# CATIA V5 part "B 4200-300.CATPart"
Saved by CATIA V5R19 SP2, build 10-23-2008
Part number: B 4200-300
Bounding box of the stored display mesh (mm): x -47.487 to 47.487, y -47.487 to 47.487, z 0 to 720
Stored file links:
  C:\Users\Bora\Desktop\3D Katı model\B serisi\B 4200\B 4200-300.CATPart
  C:\Program Files\Dassault Systemes\B19\intel_a\reffiles\standard\MetricThickPitch.txt
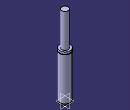
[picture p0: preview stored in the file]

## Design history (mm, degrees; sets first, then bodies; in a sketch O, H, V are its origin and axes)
Body1 (main body)
  Sketch1 on yz-plane, origin (0, 0, 0), H (0, 1, 0), V (0, 0, 1)
    point P1 (47.5, 398.5)
    point P2 (47.5, 393.5)
    point P3 (47.5, 398.5)
    point P6 (47.5, 393.5)
    point P9 (30, 719)
    point P11 (30, 719)
    arc A1 centre (47.5, 396) radius 2.5 from (47.5, 398.5) to (47.5, 393.5) ccw
    line L1 (47.5, 398.5) -> (47.5, 417)
    line L2 (47.5, 13) -> (47.5, 393.5)
    line L3 (43.5, 13) -> (43.5, 8)
    arc A2 centre (29, 719) radius 1 from (30, 719) to (29, 720) ccw
    line L4 (30, 719) -> (30, 417)
    line L5 (47.5, 0) -> (47.5, 8)
    line L6 (29, 720) -> (0, 720)
    point P15 (0, 720)
    line L7 (30, 417) -> (47.5, 417)
    line L8 (0, 0) -> (47.5, 0)
    line L9 (43.5, 13) -> (47.5, 13)
    line L10 (43.5, 8) -> (47.5, 8)
    coincidence: P15 V, P1 P3, P2 P6, P9 P11
    tangency: L6 A2
    horizontal: L7 H, L8 H, L9 H, L10 H
  Shaft1: profile Sketch1, axis Sketch1.V, angle 360
  Sketch2 on face of Shaft1 from Sketch1.L8, origin (0, 0, 0), H (1, 0, 0), V (0, -1, 0)
    point P1 (30, 0)
    distance P1 V = 30
  Hole1: placed by Sketch2, at (30, 0, 0) direction (0, 0, 1), diameter 6.647, depth 13, threaded "M8", thread diameter 8, thread depth 13, pitch 1.25
  CircPattern1: of Hole1, instances 4, angular step 90, axis from xy-plane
